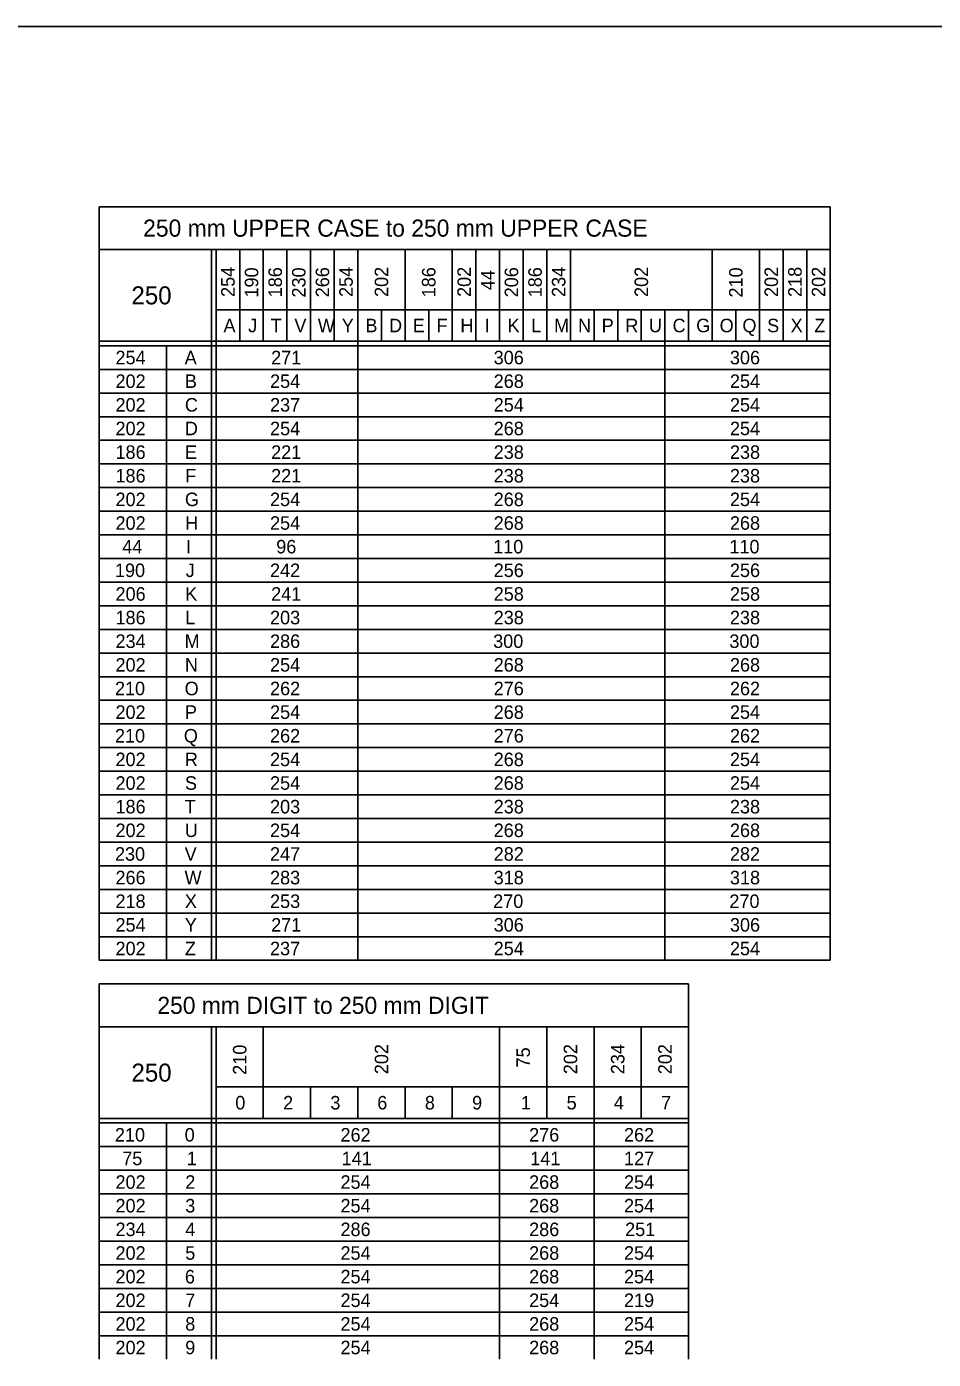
# Model space of a CAD drawing. Extents: x 637580 to 641849, y 297270 to 299646.
# Drawn here: x 638010.8 to 638212.3, y 297552.6 to 297848.6 of the extents above; entities that cross this region are included whole.
import ezdxf

# ---------------------------------------------------------------- set-up
doc = ezdxf.new("R2010")
doc.units = 0
doc.layers.add('1', color=7, linetype='Continuous')
doc.layers.add('2', color=7, linetype='Continuous')

msp = doc.modelspace()

# ---------------------------------------------------------------- linework, layer by layer
at = {"layer": '1'}
msp.add_line((637620.31, 297848.63), (638406.31, 297848.63), dxfattribs=at)
at = {"layer": '2'}
for p, q in [((638189.41, 297808.63), (638026.91, 297808.63)), ((638026.91, 297808.63), (638026.91, 297641.25)), ((638189.41, 297808.63), (638189.41, 297641.25)), ((638026.91, 297799.13), (638189.41, 297799.13)), ((638051.91, 297799.13), (638051.91, 297641.25)), ((638052.91, 297799.13), (638052.91, 297641.25)), ((638058.16, 297799.13), (638058.16, 297778.75)), ((638063.41, 297799.13), (638063.41, 297778.75)), ((638068.66, 297799.13), (638068.66, 297778.75)), ((638073.91, 297799.13), (638073.91, 297778.75)), ((638079.16, 297799.13), (638079.16, 297778.75)), ((638084.41, 297799.13), (638084.41, 297641.25)), ((638094.91, 297799.13), (638094.91, 297778.75)), ((638105.41, 297799.13), (638105.41, 297778.75)), ((638110.66, 297799.13), (638110.66, 297778.75)), ((638115.91, 297799.13), (638115.91, 297778.75)), ((638121.16, 297799.13), (638121.16, 297778.75)), ((638126.41, 297799.13), (638126.41, 297778.75)), ((638131.66, 297799.13), (638131.66, 297778.75)), ((638163.16, 297799.13), (638163.16, 297778.75)), ((638173.66, 297799.13), (638173.66, 297778.75)), ((638178.91, 297799.13), (638178.91, 297778.75)), ((638184.16, 297799.13), (638184.16, 297778.75)), ((638052.91, 297785.75), (638189.41, 297785.75)), ((638089.66, 297785.75), (638089.66, 297778.75)), ((638100.16, 297785.75), (638100.16, 297778.75)), ((638136.91, 297785.75), (638136.91, 297778.75)), ((638142.16, 297785.75), (638142.16, 297778.75)), ((638147.41, 297785.75), (638147.41, 297778.75)), ((638147.41, 297785.75), (638147.41, 297778.75)), ((638152.66, 297785.75), (638152.66, 297641.25)), ((638157.91, 297785.75), (638157.91, 297778.75)), ((638168.41, 297785.75), (638168.41, 297778.75)), ((638189.41, 297778.75), (638026.91, 297778.75)), ((638189.41, 297777.75), (638026.91, 297777.75)), ((638041.91, 297777.75), (638041.91, 297641.25)), ((638189.41, 297772.5), (638026.91, 297772.5)), ((638189.41, 297767.25), (638026.91, 297767.25)), ((638189.41, 297762), (638026.91, 297762)), ((638189.41, 297756.75), (638026.91, 297756.75)), ((638189.41, 297751.5), (638026.91, 297751.5)), ((638189.41, 297746.25), (638026.91, 297746.25)), ((638189.41, 297741), (638026.91, 297741)), ((638189.41, 297735.75), (638026.91, 297735.75)), ((638189.41, 297730.5), (638026.91, 297730.5)), ((638189.41, 297725.25), (638026.91, 297725.25)), ((638189.41, 297720), (638026.91, 297720)), ((638189.41, 297714.75), (638026.91, 297714.75)), ((638189.41, 297709.5), (638026.91, 297709.5)), ((638189.41, 297704.25), (638026.91, 297704.25)), ((638189.41, 297699), (638026.91, 297699)), ((638189.41, 297693.75), (638026.91, 297693.75)), ((638189.41, 297688.5), (638026.91, 297688.5)), ((638189.41, 297683.25), (638026.91, 297683.25)), ((638189.41, 297678), (638026.91, 297678)), ((638189.41, 297672.75), (638026.91, 297672.75)), ((638189.41, 297667.5), (638026.91, 297667.5)), ((638189.41, 297662.25), (638026.91, 297662.25)), ((638189.41, 297657), (638026.91, 297657)), ((638189.41, 297651.75), (638026.91, 297651.75)), ((638189.41, 297646.5), (638026.91, 297646.5)), ((638026.91, 297641.25), (638026.91, 297641.25)), ((638026.91, 297641.25), (638189.41, 297641.25)), ((638157.91, 297636), (638026.91, 297636)), ((638026.91, 297636), (638026.91, 297552.63)), ((638157.91, 297552.63), (638157.91, 297636)), ((638026.91, 297626.5), (638157.91, 297626.5)), ((638051.91, 297626.5), (638051.91, 297552.63)), ((638052.91, 297626.5), (638052.91, 297552.63)), ((638063.41, 297626.5), (638063.41, 297606.13)), ((638115.91, 297626.5), (638115.91, 297552.63)), ((638126.41, 297626.5), (638126.41, 297606.13)), ((638136.91, 297626.5), (638136.91, 297552.63)), ((638147.41, 297626.5), (638147.41, 297606.13)), ((638052.91, 297613.13), (638157.91, 297613.13)), ((638073.91, 297613.13), (638073.91, 297606.13)), ((638084.41, 297613.13), (638084.41, 297606.13)), ((638094.91, 297613.13), (638094.91, 297606.13)), ((638105.41, 297613.13), (638105.41, 297606.13)), ((638157.91, 297606.13), (638026.91, 297606.13)), ((638157.91, 297605.13), (638026.91, 297605.13)), ((638041.91, 297605.13), (638041.91, 297552.63)), ((638157.91, 297599.88), (638026.91, 297599.88)), ((638157.91, 297594.63), (638026.91, 297594.63)), ((638157.91, 297589.38), (638026.91, 297589.38)), ((638157.91, 297584.13), (638026.91, 297584.13)), ((638157.91, 297578.88), (638026.91, 297578.88)), ((638157.91, 297573.63), (638026.91, 297573.63)), ((638157.91, 297568.38), (638026.91, 297568.38)), ((638157.91, 297563.13), (638026.91, 297563.13)), ((638157.91, 297557.88), (638026.91, 297557.88))]:
    msp.add_line(p, q, dxfattribs=at)

# ---------------------------------------------------------------- texts
for s, height, p in [('250 mm UPPER CASE to 250 mm UPPER CASE', 3.8, (638036.7, 297801.98)), ('250', 4, (638034.1, 297786.94)), ('A', 3, (638054.56, 297780.75)), ('J', 3, (638060.04, 297780.75)), ('T', 3, (638065.04, 297780.75)), ('V', 3, (638070.31, 297780.75)), ('W', 3, (638075.53, 297780.75)), ('Y', 3, (638080.84, 297780.75)), ('B', 3, (638086.1, 297780.75)), ('D', 3, (638091.35, 297780.75)), ('E', 3, (638096.62, 297780.75)), ('F', 3, (638101.92, 297780.75)), ('H', 3, (638107.19, 297780.75)), ('I', 3, (638112.6, 297780.75)), ('K', 3, (638117.69, 297780.75)), ('L', 3, (638122.94, 297780.75)), ('M', 3, (638128.03, 297780.75)), ('N', 3, (638133.35, 297780.75)), ('P', 3, (638138.6, 297780.75)), ('R', 3, (638143.85, 297780.75)), ('U', 3, (638149.09, 297780.75)), ('C', 3, (638154.35, 297780.75)), ('G', 3, (638159.6, 297780.75)), ('O', 3, (638164.81, 297780.75)), ('Q', 3, (638169.88, 297780.75)), ('S', 3, (638175.37, 297780.75)), ('X', 3, (638180.59, 297780.75)), ('Z', 3, (638185.85, 297780.75)), ('254', 3, (638030.56, 297773.63)), ('A', 3, (638045.93, 297773.63)), ('271', 3, (638065.15, 297773.63)), ('306', 3, (638114.6, 297773.63)), ('306', 3, (638167.1, 297773.63)), ('202', 3, (638030.56, 297768.38)), ('B', 3, (638045.98, 297768.38)), ('254', 3, (638064.9, 297768.38)), ('268', 3, (638114.6, 297768.38)), ('254', 3, (638167.1, 297768.38)), ('202', 3, (638030.56, 297763.13)), ('C', 3, (638045.98, 297763.13)), ('237', 3, (638064.9, 297763.13)), ('254', 3, (638114.6, 297763.13)), ('254', 3, (638167.1, 297763.13)), ('202', 3, (638030.56, 297757.88)), ('D', 3, (638045.98, 297757.88)), ('254', 3, (638064.9, 297757.88)), ('268', 3, (638114.6, 297757.88)), ('254', 3, (638167.1, 297757.88)), ('186', 3, (638030.56, 297752.63)), ('E', 3, (638045.99, 297752.63)), ('221', 3, (638065.15, 297752.63)), ('238', 3, (638114.6, 297752.63)), ('238', 3, (638167.1, 297752.63)), ('186', 3, (638030.56, 297747.38)), ('F', 3, (638046.05, 297747.38)), ('221', 3, (638065.15, 297747.38)), ('238', 3, (638114.6, 297747.38)), ('238', 3, (638167.1, 297747.38)), ('202', 3, (638030.56, 297742.13)), ('G', 3, (638045.98, 297742.13)), ('254', 3, (638064.9, 297742.13)), ('268', 3, (638114.6, 297742.13)), ('254', 3, (638167.1, 297742.13)), ('202', 3, (638030.56, 297736.88)), ('H', 3, (638046.06, 297736.88)), ('254', 3, (638064.9, 297736.88)), ('268', 3, (638114.6, 297736.88)), ('268', 3, (638167.1, 297736.88)), ('44', 3, (638032.06, 297731.63)), ('I', 3, (638046.23, 297731.63)), ('96', 3, (638066.28, 297731.63)), ('110', 3, (638114.48, 297731.63)), ('110', 3, (638166.98, 297731.63)), ('190', 3, (638030.44, 297726.38)), ('J', 3, (638046.17, 297726.38)), ('242', 3, (638064.9, 297726.38)), ('256', 3, (638114.6, 297726.38)), ('256', 3, (638167.1, 297726.38)), ('206', 3, (638030.56, 297721.13)), ('K', 3, (638046.06, 297721.13)), ('241', 3, (638065.15, 297721.13)), ('258', 3, (638114.6, 297721.13)), ('258', 3, (638167.1, 297721.13)), ('186', 3, (638030.56, 297715.88)), ('L', 3, (638046.06, 297715.88)), ('203', 3, (638064.9, 297715.88)), ('238', 3, (638114.6, 297715.88)), ('238', 3, (638167.1, 297715.88)), ('234', 3, (638030.56, 297710.63)), ('M', 3, (638045.91, 297710.63)), ('286', 3, (638064.9, 297710.63)), ('300', 3, (638114.48, 297710.63)), ('300', 3, (638166.98, 297710.63)), ('202', 3, (638030.56, 297705.38)), ('N', 3, (638045.98, 297705.38)), ('254', 3, (638064.9, 297705.38)), ('268', 3, (638114.6, 297705.38)), ('268', 3, (638167.1, 297705.38)), ('210', 3, (638030.44, 297700.13)), ('O', 3, (638045.93, 297700.13)), ('262', 3, (638064.9, 297700.13)), ('276', 3, (638114.6, 297700.13)), ('262', 3, (638167.1, 297700.13)), ('202', 3, (638030.56, 297694.88)), ('P', 3, (638045.98, 297694.88)), ('254', 3, (638064.9, 297694.88)), ('268', 3, (638114.6, 297694.88)), ('254', 3, (638167.1, 297694.88)), ('210', 3, (638030.44, 297689.63)), ('Q', 3, (638045.75, 297689.63)), ('262', 3, (638064.9, 297689.63)), ('276', 3, (638114.6, 297689.63)), ('262', 3, (638167.1, 297689.63)), ('202', 3, (638030.56, 297684.38)), ('R', 3, (638045.98, 297684.38)), ('254', 3, (638064.9, 297684.38)), ('268', 3, (638114.6, 297684.38)), ('254', 3, (638167.1, 297684.38)), ('202', 3, (638030.56, 297679.13)), ('S', 3, (638045.99, 297679.13)), ('254', 3, (638064.9, 297679.13)), ('268', 3, (638114.6, 297679.13)), ('254', 3, (638167.1, 297679.13)), ('186', 3, (638030.56, 297673.88)), ('T', 3, (638045.92, 297673.88)), ('203', 3, (638064.9, 297673.88)), ('238', 3, (638114.6, 297673.88)), ('238', 3, (638167.1, 297673.88)), ('202', 3, (638030.56, 297668.63)), ('U', 3, (638045.97, 297668.63)), ('254', 3, (638064.9, 297668.63)), ('268', 3, (638114.6, 297668.63)), ('268', 3, (638167.1, 297668.63)), ('230', 3, (638030.44, 297663.38)), ('V', 3, (638045.93, 297663.38)), ('247', 3, (638064.9, 297663.38)), ('282', 3, (638114.6, 297663.38)), ('282', 3, (638167.1, 297663.38)), ('266', 3, (638030.56, 297658.13)), ('W', 3, (638045.91, 297658.13)), ('283', 3, (638064.9, 297658.13)), ('318', 3, (638114.6, 297658.13)), ('318', 3, (638167.1, 297658.13)), ('218', 3, (638030.56, 297652.88)), ('X', 3, (638045.97, 297652.88)), ('253', 3, (638064.9, 297652.88)), ('270', 3, (638114.48, 297652.88)), ('270', 3, (638166.98, 297652.88)), ('254', 3, (638030.56, 297647.63)), ('Y', 3, (638045.97, 297647.63)), ('271', 3, (638065.15, 297647.63)), ('306', 3, (638114.6, 297647.63)), ('306', 3, (638167.1, 297647.63)), ('202', 3, (638030.56, 297642.38)), ('Z', 3, (638045.98, 297642.38)), ('237', 3, (638064.9, 297642.38)), ('254', 3, (638114.6, 297642.38)), ('254', 3, (638167.1, 297642.38)), ('250 mm DIGIT to 250 mm DIGIT', 3.8, (638039.86, 297629.35)), ('250', 4, (638034.1, 297614.31)), ('0', 3, (638057.18, 297608.13)), ('2', 3, (638067.81, 297608.13)), ('3', 3, (638078.31, 297608.13)), ('6', 3, (638088.73, 297608.13)), ('8', 3, (638099.31, 297608.13)), ('9', 3, (638109.8, 297608.13)), ('1', 3, (638120.65, 297608.13)), ('5', 3, (638130.81, 297608.13)), ('4', 3, (638141.31, 297608.13)), ('7', 3, (638151.81, 297608.13)), ('210', 3, (638030.43, 297601)), ('0', 3, (638045.93, 297601)), ('262', 3, (638080.56, 297601)), ('276', 3, (638122.48, 297601)), ('262', 3, (638143.56, 297601)), ('75', 3, (638032.06, 297595.75)), ('1', 3, (638046.4, 297595.75)), ('141', 3, (638080.81, 297595.75)), ('141', 3, (638122.73, 297595.75)), ('127', 3, (638143.56, 297595.75)), ('202', 3, (638030.56, 297590.5)), ('2', 3, (638046.06, 297590.5)), ('254', 3, (638080.56, 297590.5)), ('268', 3, (638122.48, 297590.5)), ('254', 3, (638143.56, 297590.5)), ('202', 3, (638030.56, 297585.25)), ('3', 3, (638046.06, 297585.25)), ('254', 3, (638080.56, 297585.25)), ('268', 3, (638122.48, 297585.25)), ('254', 3, (638143.56, 297585.25)), ('234', 3, (638030.56, 297580)), ('4', 3, (638046.06, 297580)), ('286', 3, (638080.56, 297580)), ('286', 3, (638122.48, 297580)), ('251', 3, (638143.81, 297580)), ('202', 3, (638030.56, 297574.75)), ('5', 3, (638046.06, 297574.75)), ('254', 3, (638080.56, 297574.75)), ('268', 3, (638122.48, 297574.75)), ('254', 3, (638143.56, 297574.75)), ('202', 3, (638030.56, 297569.5)), ('6', 3, (638045.98, 297569.5)), ('254', 3, (638080.56, 297569.5)), ('268', 3, (638122.48, 297569.5)), ('254', 3, (638143.56, 297569.5)), ('202', 3, (638030.56, 297564.25)), ('7', 3, (638046.06, 297564.25)), ('254', 3, (638080.56, 297564.25)), ('254', 3, (638122.48, 297564.25)), ('219', 3, (638143.56, 297564.25)), ('202', 3, (638030.56, 297559)), ('8', 3, (638046.06, 297559)), ('254', 3, (638080.56, 297559)), ('268', 3, (638122.48, 297559)), ('254', 3, (638143.56, 297559)), ('202', 3, (638030.56, 297553.75)), ('9', 3, (638046.05, 297553.75)), ('254', 3, (638080.56, 297553.75)), ('268', 3, (638122.48, 297553.75)), ('254', 3, (638143.56, 297553.75))]:
    msp.add_text(s, height=height, dxfattribs=at).set_placement(p)
for s, p in [('254', (638057.04, 297788.59)), ('190', (638062.29, 297788.46)), ('186', (638067.54, 297788.51)), ('230', (638072.79, 297788.46)), ('266', (638078.04, 297788.51)), ('254', (638083.29, 297788.59)), ('202', (638091.16, 297788.59)), ('186', (638101.66, 297788.51)), ('202', (638109.54, 297788.59)), ('44', (638114.79, 297790.09)), ('206', (638120.04, 297788.51)), ('186', (638125.29, 297788.51)), ('234', (638130.54, 297788.59)), ('202', (638148.91, 297788.59)), ('210', (638169.91, 297788.46)), ('202', (638177.79, 297788.59)), ('218', (638183.04, 297788.59)), ('202', (638188.29, 297788.59)), ('210', (638059.66, 297615.83)), ('202', (638091.16, 297615.96)), ('202', (638133.16, 297615.96)), ('234', (638143.66, 297615.96)), ('202', (638154.16, 297615.96)), ('75', (638122.66, 297617.46))]:
    msp.add_text(s, height=3, rotation=90, dxfattribs=at).set_placement(p)

doc.saveas('drawing.dxf')
